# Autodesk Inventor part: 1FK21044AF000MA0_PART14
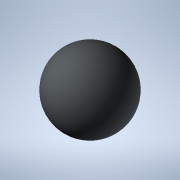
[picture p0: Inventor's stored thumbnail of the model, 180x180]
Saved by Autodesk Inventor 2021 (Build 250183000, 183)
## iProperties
Created: 2025-04
Part Number: 1FK21044AF000MA0_PART14
Material: Generic
Catalog Web Link: www.3dfindit.com
Description: -Servo synchronous motor
Document SubType Name: Modeling
Designer: psAdmin
Mass: 0.137258 g
Surface Area: 1.2868 cm^2
Volume: 0.137258 cm^3
Density: 1 g/cm^3
Appearance: PSOLRGB-212-217-219
Category: PARTsolutions
Title: 1FK21044AF000MA0_PART14
Author: Cadenas PARTsolutions
Comments: Servo synchronous motor
Sending System: PARTsolutions
Preprocessor: ST-DEVELOPER v19.3
PSOL_IDENT_0: {$CADENAS_DATA/23d-libs/siemens_ag/_cat_/39/c4/1fk21044af000ma0.prj},216 {VTYP=3D},{NB=1FK21044AF000
PSOL_IDENT_1: MA0_PART14},{LINA=1FK21044AF000MA0_PART14},{NN=1FK21044AF000MA0_PART14},{NOPRJ=TRUE},{DATE=19.08.202
PSOL_IDENT_2: 5 14:00:33},{GEOMDATE=30.07.2025 02:02:22},{VERSION=},{LINEID=10},{WBVAR=},{WBNUMERIC=}  {NB=1FK2104
PSOL_IDENT_3: 4AF000MA0_PART14},{LINA=1FK21044AF000MA0_PART14},{KT=DUMMY},{PREVIEW=../../../_pool_/cb/72/p_d211_xx
PSOL_IDENT_4: _00434j.png},{DESCSHORT=SIMOTICS S-1FK2 HD, SINAMICS S210 3AC 400V-480V, 1.27 Nm, 3000 rpm},{DESCLON
PSOL_IDENT_5: G=SIMOTICS S-1FK2 HD servo motor M0=1.27 Nm; PN = 0.4 kW at nN=3000 rpm (380-480 V); PN = 0.2 kW at
PSOL_IDENT_6: nN=1500 rpm (200-240 V); degree of protection IP64; cylindrical shaft D19x40mm; absolute encoder 22-
PSOL_IDENT_7: bit + 12-bit multiturn (encoder AM22DQC); with OCC interface; plug size M17, rotatable; SIMOTICS S-1
PSOL_IDENT_8: FK2 servomotorfor a wide range of uses in industrial environments. SIMOTICS S‑1FK2 servomotors are c
PSOL_IDENT_9: ompact synchronous motors with a high dynamic performance that set themselves apart as a result of t
PSOL_IDENT_10: heir high power density, degree of protection and overload capability. The motors are available in t
PSOL_IDENT_11: wo variants: as High Dynamic variant (highest dynamic performance as a result of the low intrinsic m
PSOL_IDENT_12: oment of inertia for applications demanding a high dynamic performance with low moved masses) - and
PSOL_IDENT_13: as Compact variant (precise and stable closed-loop control for medium up to large moved masses as a
PSOL_IDENT_14: result of a medium intrinsic moment of inertia). SIMOTICSS‑1FK2 servomotors fully exploit their stre
PSOL_IDENT_15: ngths in a system with the SINAMICSS210 frequency converter and simple connection using the one cabl
PSOL_IDENT_16: e connection (OCC). Advantages include the short control and positioning times, fast and precise cor
PSOL_IDENT_17: rection of disturbing quantities as well as stable control with a high dynamic performance. The serv
PSOL_IDENT_18: o motors can be configured to address a wide range of requirements. For example with and without hol
PSOL_IDENT_19: ding brake, IP64 or IP65 degree of protection, singleturn or multiturn absolute encoders - to name j
PSOL_IDENT_20: ust a few. Further, the servomotors are available in different shaft heights extending from 20 to 10
PSOL_IDENT_21: 0. A shaft sealing ring is available to achieve an IP65 degree of protection and for subsequent moun
PSOL_IDENT_22: ting at the motor or as spare part. SIMOTICS - the optimum motor for each and every motion control a
PSOL_IDENT_23: pplication.},{INTNO=804766906428},{SUPPLIERALTNO=1FK2104-4AF00-0MA0},{MANUID=1FK21044AF000MA0},{MANU
PSOL_IDENT_24: NAME=Siemens},{MANUTYPEDESC=Synchronous motor 1FK2-HD 1.27 NM},{AAU732=SIMOTICS},{AAO057=S-1FK2},{AA
PSOL_IDENT_25: U734=SIMOTICS S-1FK2 HD servo motor M0=1.27 Nm; PN = 0.4 kW at nN=3000 rpm (380-480 V); PN = 0.2 kW
PSOL_IDENT_26: at nN=1500 rpm (200-240 V); degree of protection IP64; cylindrical shaft D19x40mm; absolute encoder
PSOL_IDENT_27: 22-bit + 12-bit multiturn (encoder AM22DQC); with OCC interface; plug size M17, rotatable;},{AAW338=
PSOL_IDENT_28: Synchronous motor 1FK2-HD 1.27 NM},{AAO742=SIMOTICS},{AAO663=4042948693322},{NOCUPEROU=1},{PRICEQUAN
PSOL_IDENT_29: TITY=1},{QUANTITYMIN=1},{QUANTITYINT=1},{CTN=85015100},{COO=DE},{AAO676=1FK2104-4AF00-0MA0},{AAO677=
PSOL_IDENT_30: Siemens AG},{ORDERUNIT=C62},{CONTENTUNIT=C62}
NB: 1FK21044AF000MA0_PART14
NT: Servo synchronous motor
NBSYN: $MANUID._PART14
LINA: 1FK21044AF000MA0_PART14
CATALOG: SIEMENS
PREVIEW: ../../../_pool_/cb/72/p_d211_xx_00434j.png
DESCSHORT: SIMOTICS S-1FK2 HD, SINAMICS S210 3AC 400V-480V, 1.27 Nm, 3000 rpm
DESCLONG: SIMOTICS S-1FK2 HD servo motor M0=1.27 Nm; PN = 0.4 kW at nN=3000 rpm (380-480 V); PN = 0.2 kW at nN=1500 rpm (200-240 V); degree of protection IP64; cylindrica
INTNO: 804766906428
SUPPLIERALTNO: 1FK2104-4AF00-0MA0
MANUID: 1FK21044AF000MA0
MANUNAME: Siemens
MANUTYPEDESC: Synchronous motor 1FK2-HD 1.27 NM
AAU732: SIMOTICS
AAO057: S-1FK2
AAU734: SIMOTICS S-1FK2 HD servo motor M0=1.27 Nm; PN = 0.4 kW at nN=3000 rpm (380-480 V); PN = 0.2 kW at nN=1500 rpm (200-240 V); degree of protection IP64; cylindrica
AAW338: Synchronous motor 1FK2-HD 1.27 NM
AAO742: SIMOTICS
AAO663: 4042948693322.0
NOCUPEROU: 1
PRICEQUANTITY: 1
QUANTITYMIN: 1
QUANTITYINT: 1
CTN: 85015100
COO: DE
ARTICLENO: 1FK21044AF000MA0_PART14
BOMINFO: 1FK21044AF000MA0_PART14
CREATOR: CADENAS GmbH
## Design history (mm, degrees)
feature "2025_04_17_15_01_28_0038"
body "Solid1"
